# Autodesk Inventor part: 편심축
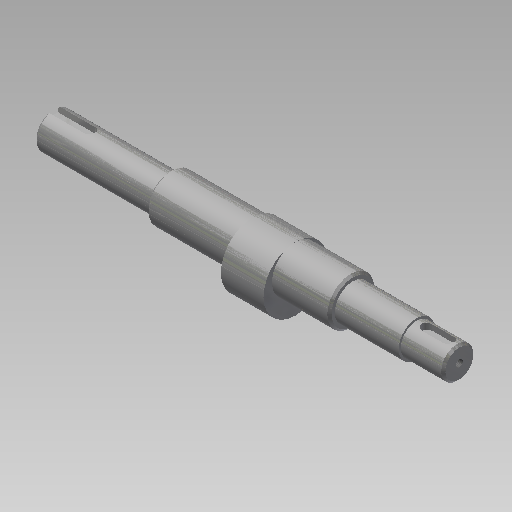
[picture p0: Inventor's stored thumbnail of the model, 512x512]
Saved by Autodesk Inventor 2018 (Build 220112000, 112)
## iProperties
Created: 2016-05
Part Number: 편심축
Document SubType Name: Modeling
Designer: mduedu
Density: 7.86 g/cm^3
Material: 강철, 연강
Appearance: 강철
Author: mduedu
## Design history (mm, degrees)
sketch "스케치1"
  geometry: L1 (-40.5, 11)-(-40.5, 8.5); L2 (45.5, 11)-(45.5, 8.5); L3 (-95.5, 0)-(95.5, 0); L4 (-40.5, 11)-(45.5, 11); L5 (45.5, 11)-(45.5, 8.5); L6 (-40.5, 11)-(-40.5, 8.5); L7 (-40.5, 8.5)-(-95.5, 8.5); L8 (-95.5, 8.5)-(-95.5, 0); L9 (45.5, 8.5)-(75.5, 8.5); L10 (95.5, 7.5)-(95.5, 0); L11 (75.5, 8.5)-(75.5, 7.5); L12 (75.5, 7.5)-(95.5, 7.5); 1 further point
  constraints: 24 end point, 9 perpendicular, 2 midpoint, 1 collinear, 1 horizontal
  dimensions: "d0" = 22 diameter of L4 L3; "d1" = 17 diameter of L7 L3; "d2" = 55 distance between parallel lines of L8 L1; "d3" = 50 distance between parallel lines of L10 L2; "d4" = 15 diameter of L12 L3; "d5" = 20 distance between parallel lines of L10 L11; "d29" = 86 distance of L1.start L2.start
revolve "회전1" stored, may be unused: angle "d6" = 90 deg
node "작업 평면7"
node "작업 평면9"
sketch "스케치2"
  geometry: C1 r 11 at (0, 0); C2 r 15 at (0, -4); C3 r 11 at (0, 0); 2 further points
  constraints: 3 centre point, 2 coincident, 1 concentric, 1 vertical alignment
  dimensions: "d9" = 4 distance of point (0, 0) C2.centre; "d10" = 30 diameter of C2
extrude "돌출1" join sketch "스케치2" stored distance "d11" = 20; taper "d12" = 0 deg
chamfer "모따기1" distance "d17" = 1; stored, may be unused: second distance "d18" = 2, angle "d19" = 45 deg
node "작업 평면4"
sketch "스케치4"
  geometry: L1 (-10, -6.5)-(-10, 6.5) reference; L2 (-5, 2.5)-(5, 2.5); L3 (5, -2.5)-(-5, -2.5); A1 r 2.5 centre (5, 0) between (5, -2.5) and (5, 2.5); A2 r 2.5 centre (-5, 0) between (-5, 2.5) and (-5, -2.5); 2 further points
  constraints: 4 end point, 4 point on circle, 4 tangent, 2 centre point, 1 horizontal alignment, 1 midpoint, 1 parallel, 1 perpendicular
  dimensions: "d20" = 5 distance between parallel lines of L3 L2; "d21" = 15 dimension on A1 A2; "d22" = 2.5 distance edge to line of A2 L1
extrude "돌출3" cut sketch "스케치4" distance "d23" = 3; taper "d24" = 0 deg
node "작업 평면5"
sketch "스케치5"
  geometry: L1 (27.5, 7.5)-(27.5, -7.5) reference; L2 (27.5, 2.5)-(10, 2.5); L3 (10, -2.5)-(27.5, -2.5); A1 r 2.5 centre (10, 0) between (10, 2.5) and (10, -2.5); 2 further points
  constraints: 4 end point, 2 perpendicular, 2 point on circle, 2 point on line, 2 tangent, 1 centre point, 1 horizontal alignment, 1 midpoint
  dimensions: "d25" = 5 distance between parallel lines of L3 L2; "d26" = 20 dimension on A1 L1
extrude "돌출4" cut sketch "스케치5" distance "d27" = 3; taper "d28" = 0 deg
hole "구멍1" diameter "d34" = 3.242; stored, may be unused: countersink angle "d38" = 90 deg, drill point angle "d40" = 118 deg; dims "d35" = 9, "d36" = 4, "d37" = 2, "d39" = 11, "d43" = 10, "d44" = 10
node "솔리드1"
other parameters: "d31" = -37
